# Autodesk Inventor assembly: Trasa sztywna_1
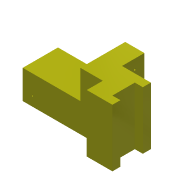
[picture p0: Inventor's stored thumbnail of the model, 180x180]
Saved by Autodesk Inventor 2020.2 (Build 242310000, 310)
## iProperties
Created: 2014-07
Part Number: Trasa sztywna_1
Document SubType Name: Assembly
Designer: F.Stasiak
Catalog Web Link: www.expertbooks.pl
Manager: www.cadconsulting.pl
Company: Fabian Stasiak CAD Consulting
Author: F.Stasiak
Subject: Zbiór ćwiczeń. Autodesk Inventor 2020. Kurs Professional
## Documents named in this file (2)
- C:\2020_Kurs_Professional\R1 Rury\Trasa sztywna_1.iam
- C:\2020_Kurs_Professional\R1 Rury\Konstrukcja_1.ipt
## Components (1 placed, 1 different names)
1. Konstrukcja_1:1
